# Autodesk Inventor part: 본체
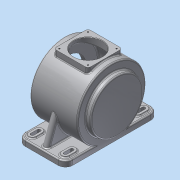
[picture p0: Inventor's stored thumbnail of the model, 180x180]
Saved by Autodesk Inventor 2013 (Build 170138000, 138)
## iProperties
Created: 2015-06
Part Number: 본체
Material: 알루미늄 6061
Document SubType Name: Modeling
Designer: Administrator
Density: 2.71 g/cm^3
Mass: 3326.36 g
Surface Area: 2312.89 cm^2
Volume: 1227.44 cm^3
Author: Administrator
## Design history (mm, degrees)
sketch "스케치1"
  geometry: L1 (-59, 115)-(59, 115); L2 (59, 115)-(59, -115); L3 (59, -115)-(-59, -115); L4 (-59, -115)-(-59, 115); L5 (-59, -115)-(59, 115); 2 further points
  constraints: 10 end point, 2 parallel, 1 coincident, 1 horizontal, 1 midpoint, 1 perpendicular
  dimensions: "d0" = 118 distance of L2.end L3.end; "d1" = 230 distance of L1.end L2.end
extrude "돌출1" new body sketch "스케치1" distance "d2" = 14; taper "d3" = 0 deg
sketch "스케치2"
  geometry: L1 (0, 0)-(0, 230) reference; L2 (0, 230)-(14, 230) reference; L3 (170, 202.523)-(170, -41.172); C1 r 85 at (85, 115); 2 further points
  constraints: 2 end point, 1 centre point, 1 horizontal alignment, 1 midpoint, 1 perpendicular
  dimensions: "d4" = 170 diameter of C1; "d6" = 85 distance from line of L3 C1.centre; "d59" = 85 distance from line of L1 C1.centre
extrude "돌출2" join sketch "스케치2" distance "d7" = 118; taper "d8" = 0 deg
sketch "스케치4"
  geometry: C1 r 65 at (-85, 115); A1 r 85 centre (-85, 115) between (-14, 161.733) and (-14, 68.267) reference; 1 further point
  constraints: 1 centre point, 1 coincident
  dimensions: "d12" = 130 diameter of C1
extrude "돌출4" join sketch "스케치4" distance "d13" = 13; taper "d14" = 0 deg
fillet "모깎기1" dims "d15" = 18
sketch "스케치5"
  geometry: C1 r 65 at (0, 0); A1 r 85 centre (0, 0) between (-71, -46.733) and (-71, 46.733) reference; 1 further point
  constraints: 1 centre point, 1 coincident
  dimensions: "d16" = 130 diameter of C1
extrude "돌출5" join sketch "스케치5" distance "d17" = 3; taper "d18" = 0 deg
node "작업 평면1"
sketch "스케치6"
  geometry: L1 (-35.5, -42.5)-(35.5, -42.5); L2 (42.5, -35.5)-(42.5, 35.5); L3 (35.5, 42.5)-(-35.5, 42.5); L4 (-42.5, 35.5)-(-42.5, -35.5); L5 (-42.5, -42.5)-(42.5, 42.5); A1 r 7 centre (-35.5, 35.5) between (-35.5, 42.5) and (-42.5, 35.5); A2 r 7 centre (35.5, 35.5) between (42.5, 35.5) and (35.5, 42.5); A3 r 7 centre (35.5, -35.5) between (35.5, -42.5) and (42.5, -35.5); A4 r 7 centre (-35.5, -35.5) between (-42.5, -35.5) and (-35.5, -42.5); 4 further points
  constraints: 10 end point, 8 point on circle, 8 point on line, 8 tangent, 4 centre point, 3 equal radius, 2 parallel, 1 coincident, 1 horizontal, 1 midpoint, 1 perpendicular
  dimensions: "d20" = 85 distance of point (-42.5, 42.5) L5.end; "d21" = 85 distance of L5.end point (42.5, -42.5); "d107" = 7 radius of A1
extrude "돌출6" join sketch "스케치6" stored distance "d22" = 3; taper "d23" = 0 deg
sketch "스케치7"
  geometry: L1 (-41, -115)-(41, -115) reference; L2 (59, -97)-(59, -46.733) reference; L3 (41, -72)-(41, -72); L4 (50, -81)-(50, -97); L5 (41, -106)-(41, -106); L6 (32, -97)-(32, -81); A1 r 9 centre (41, -97) between (41, -106) and (50, -97); A2 r 9 centre (41, -97) between (32, -97) and (41, -106); A3 r 9 centre (41, -81) between (41, -72) and (32, -81); A4 r 9 centre (41, -81) between (50, -81) and (41, -72); 4 further points
  constraints: 8 end point, 8 point on circle, 8 tangent, 6 point on line, 4 centre point, 3 equal radius, 2 parallel, 1 horizontal, 1 perpendicular
  dimensions: "d33" = 18 distance of point (50, -106) point (32, -106); "d34" = 34 distance of point (50, -72) point (50, -106); "d35" = 9 distance between parallel lines of L2 L4; "d36" = 9 distance between parallel lines of L1 L5; "d37" = 9 radius of A1
extrude "돌출7" join sketch "스케치7" distance "d31" = 3; taper "d32" = 0 deg
sketch "스케치8"
  geometry: L1 (-9, -16)-(-9, 0) reference; L2 (9, 0)-(9, -16) reference; L3 (-4, 4)-(4, 4); L4 (4, 4)-(4, -20); L5 (4, -20)-(-4, -20); L6 (-4, -20)-(-4, 4); A1 r 9 centre (0, 0) between (9, 0) and (-9, 0) reference; A2 r 9 centre (0, -16) between (-9, -16) and (9, -16) reference; A3 r 9 centre (0, 0) between (9, 0) and (-9, 0) reference; 1 further point
  constraints: 8 end point, 2 parallel, 1 horizontal, 1 perpendicular
  dimensions: "d41" = 5 distance between parallel lines of L1 L6; "d42" = 5 distance between parallel lines of L2 L4; "d43" = 4 distance from line of A1.centre L3; "d44" = 4 distance from line of A2.centre L5
extrude "돌출8" cut sketch "스케치8" stored distance "d45" = 3; taper "d46" = 0 deg
fillet "모깎기3" dims "d47" = 4
node "작업 평면5"
sketch "스케치9"
  geometry: L1 (71, -109)-(-9, -79.882); L2 (-9, -79.882)-(-9, 79.882); L3 (-9, 79.882)-(71, 109); L4 (71, 109)-(71, -109); L5 (85, -97)-(85, 97) reference; L6 (71, -46.733)-(71, -97) reference; L7 (85, -115)-(71, -115) reference; L8 (71, 115)-(85, 115) reference; L9 (71, -115)-(71, -97) reference; L10 (71, 97)-(71, 115) reference; 1 further point
  constraints: 8 end point, 1 collinear, 1 parallel, 1 vertical
  dimensions: "d49" = 6 distance from line of L7 L1.start; "d50" = 6 distance from line of L8 L3.end; "d51" = 110 deg angle of L9 L1; "d52" = 110 deg angle of L10 L3; "d53" = 80 distance between parallel lines of L2 L4
extrude "돌출9" join sketch "스케치9" stored distance "d54" = 15; taper "d55" = 0 deg
fillet "모깎기4" dims "d56" = 7.5
fillet "모깎기5" dims "d57" = 3
sketch "스케치10"
  geometry: L1 (-61.5, 85)-(62, 85); L2 (-41, 0)-(41, 0) reference; L3 (59, 150)-(62, 150) reference; L4 (59, 20)-(62, 20) reference; L5 (-61.5, 85)-(-61.5, 108.5); L6 (-61.5, 108.5)-(-47.5, 108.5); L7 (-47.5, 108.5)-(-47.5, 114.368); L8 (-47.5, 114.368)-(-51, 116); L9 (-51, 116)-(-51, 162); L10 (-51, 162)-(51, 162); L11 (51, 162)-(51, 132.5); L12 (51, 132.5)-(62, 132.5); L13 (62, 132.5)-(62, 85); L14 (62, 20)-(62, 150) reference; 1 further point
  constraints: 20 end point, 5 parallel, 3 perpendicular, 1 collinear, 1 horizontal
  dimensions: "d58" = 85 distance between parallel lines of L1 L2; "d60" = 115 deg angle of L9 L8; "d61" = 95 diameter of L12 L1; "d62" = 154 diameter of L10 L1; "d63" = 11 distance between parallel lines of L11 L13; "d64" = 102 distance of L9.end L10.end; "d66" = 47 diameter of L6 L1; "d67" = 14 distance of L5.end L6.end; "d68" = 3.5 distance between parallel lines of L9 L7; "d108" = 62 diameter of L8.end L1
revolve "회전1" sketch "스케치10" stored, may be unused: angle "d69" = 90 deg
sketch "스케치13"
  geometry: C1 r 23.5 at (0, 0) reference; C2 r 15 at (0, 0); 1 further point
  constraints: 1 centre point, 1 coincident
  dimensions: "d70" = 30 diameter of C2
extrude "돌출10" cut sketch "스케치13" distance "d71" = 3; taper "d72" = 0 deg
fillet "모깎기6" dims "d73" = 3
fillet "모깎기7" dims "d74" = 0.3
fillet "모깎기8" dims "d75" = 3
fillet "모깎기9" dims "d76" = 3
sketch "스케치14"
  geometry: C1 r 35 at (0, 0); 1 further point
  constraints: 1 centre point, 1 coincident
  dimensions: "d77" = 70 diameter of C1
extrude "돌출11" cut sketch "스케치14" stored distance "d78" = 3; taper "d79" = 0 deg
chamfer "모따기1" distance "d80" = 1; stored, may be unused: second distance "d81" = 2, angle "d82" = 45 deg
sketch "스케치15"
  geometry: C1 r 47.5 at (0, 0) reference; 2 further points
  constraints: 1 horizontal alignment
  dimensions: "d83" = 55 distance of C1.centre point (55, 0)
hole "구멍1" sketch "스케치15" at (55, 0) diameter "d84" = 3.242; stored, may be unused: countersink angle "d88" = 90 deg, drill point angle "d90" = 118 deg; dims "d85" = 10, "d86" = 4, "d87" = 2, "d89" = 13
sketch "스케치16"
  geometry: A1 r 7 centre (-35.5, -35.5) between (-42.5, -35.5) and (-35.5, -42.5) reference
hole "구멍2" sketch "스케치16" at (-35.5, -35.5) diameter "d94" = 3.242; stored, may be unused: countersink angle "d98" = 90 deg, drill point angle "d100" = 118 deg; dims "d95" = 10, "d96" = 4, "d97" = 2, "d99" = 13
fillet "모깎기10" dims "d101" = 3
fillet "모깎기11" dims "d102" = 3
fillet "모깎기12" dims "d103" = 3
fillet "모깎기13" dims "d104" = 3
fillet "모깎기14" dims "d105" = 3
fillet "모깎기15" dims "d109" = 3
node "솔리드1"
mirror "대칭1"
mirror "대칭2"
mirror "대칭3"
mirror "대칭4"
pattern_circular "원형 패턴1" dims angle "d92" = 360 deg
mirror "대칭5"
mirror "대칭6"
node "작업 평면2"
node "작업 평면3"
node "작업 평면4"
other parameters: "d19" = 173, "d48" = -72
